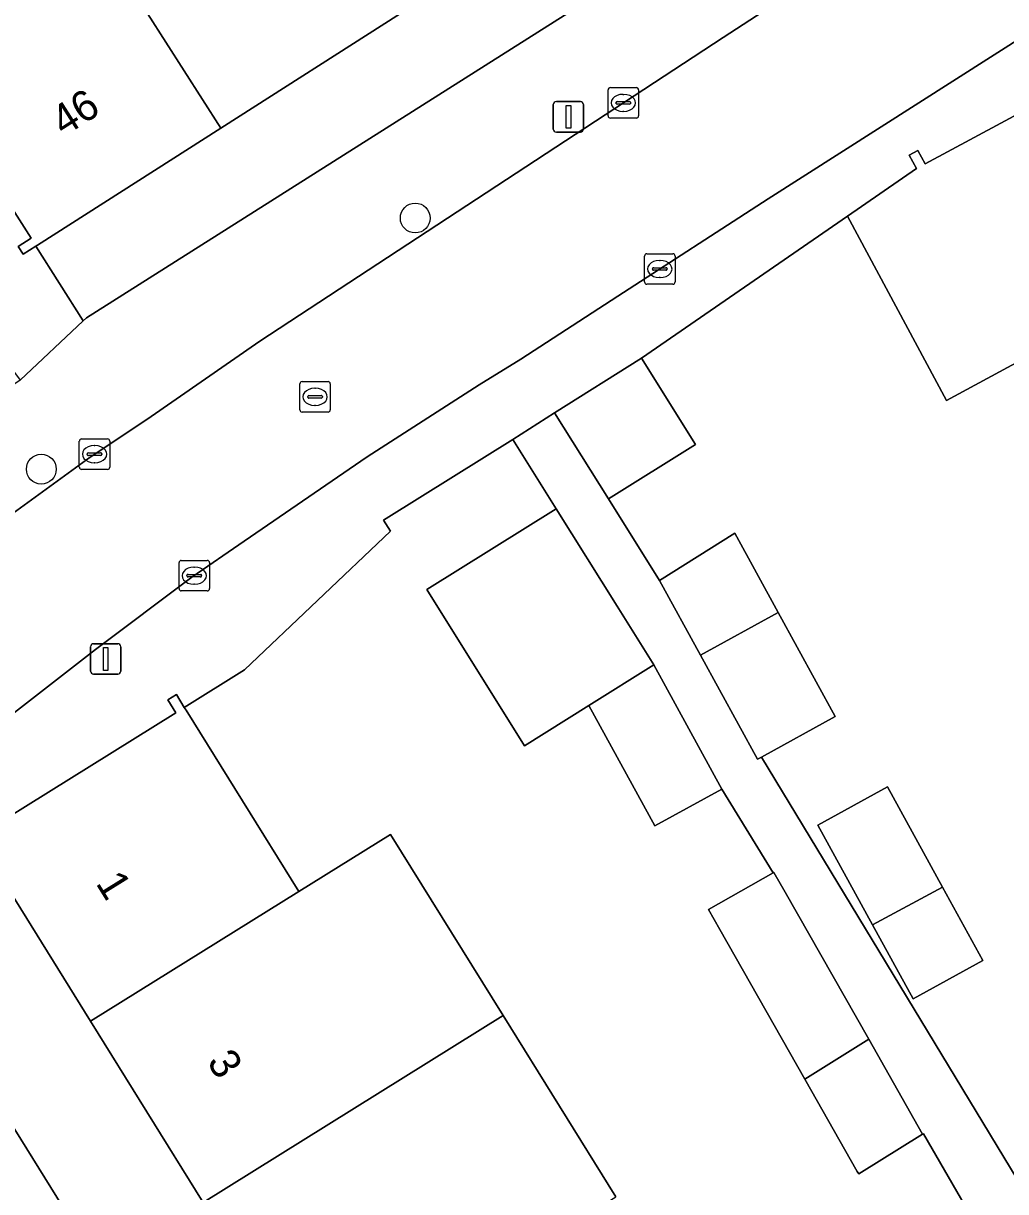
# Model space of a CAD drawing. Extents: x 162523 to 163266, y 381230 to 382050.
# Drawn here: x 162708.58 to 162740.82, y 381862.71 to 381901.03 of the extents above; entities that cross this region are included whole.
import ezdxf

# ---------------------------------------------------------------- set-up
doc = ezdxf.new("R2010")
doc.units = 0
for name, color, linetype in [('IMGEO_Boom', 7, 'Continuous'), ('IMGEO_Erf', 7, 'Continuous'), ('IMGEO_Kolk', 7, 'Continuous'), ('IMGEO_Lichtmast', 7, 'Continuous'), ('IMGEO_Muur', 7, 'Continuous'), ('IMGEO_Pand', 7, 'Continuous'), ('IMGEO_Pand_nummerreeks', 7, 'Continuous'), ('IMGEO_Rijbaan_lokaal_open', 7, 'Continuous'), ('IMGEO_Rioolput', 7, 'Continuous'), ('IMGEO_Voetpad_gesloten', 7, 'Continuous'), ('IMGEO_Voetpad_open', 7, 'Continuous')]:
    doc.layers.add(name, color=color, linetype=linetype)

msp = doc.modelspace()

# ---------------------------------------------------------------- linework, layer by layer
at = {"layer": 'IMGEO_Boom'}
for centre in [(162721.443, 381894.646), (162709.174, 381886.41)]:
    msp.add_circle(centre, 0.489, dxfattribs=at)
at = {"layer": 'IMGEO_Erf'}
for points in [[(162762.533, 381924.202), (162770.37, 381928.325), (162768.294, 381931.56), (162762.269, 381927.716), (162756.368, 381923.951), (162750.467, 381920.185), (162744.565, 381916.42), (162738.665, 381912.655), (162732.763, 381908.889), (162726.862, 381905.124), (162720.96, 381901.359), (162715.059, 381897.593), (162709.052, 381893.761), (162708.999, 381893.727), (162710.551, 381891.275), (162710.655, 381891.373)], [(162738.745, 381872.704), (162740.068, 381870.292), (162737.778, 381869.037), (162736.446, 381871.468), (162734.654, 381874.735), (162736.943, 381875.99)]]:
    msp.add_lwpolyline(points, close=True, dxfattribs=at)
for points in [[(162757.857, 381859.135), (162754.542, 381865.3), (162751.226, 381871.465), (162749.501, 381874.674), (162745.998, 381872.79), (162744.408, 381875.746), (162745.415, 381876.288), (162742.291, 381882.096), (162744.788, 381883.439), (162744.596, 381883.796), (162741.28, 381889.961), (162738.872, 381888.666), (162735.626, 381894.706), (162728.869, 381890.045), (162730.638, 381887.218), (162727.784, 381885.433), (162729.455, 381882.762), (162731.926, 381884.308), (162733.354, 381881.705), (162735.225, 381878.293), (162732.802, 381876.964), (162741.663, 381862.35), (162743.847, 381863.545), (162745.536, 381860.46)], [(162752.78, 381839.267), (162738.115, 381864.612), (162738.091, 381864.598), (162735.994, 381863.292), (162735.947, 381863.374), (162734.225, 381866.406), (162731.437, 381871.315), (162731.067, 381871.965), (162733.19, 381873.172), (162731.503, 381875.915), (162729.304, 381874.708), (162727.137, 381878.659), (162725.028, 381877.339), (162721.825, 381882.459), (162726.064, 381885.112), (162724.642, 381887.384), (162721.68, 381885.531), (162720.403, 381884.732), (162720.626, 381884.376), (162715.845, 381879.824), (162713.866, 381878.593), (162713.925, 381878.499), (162717.621, 381872.559), (162720.626, 381874.429), (162724.325, 381868.486), (162728.024, 381862.543)], [(162714.489, 381862.36), (162710.79, 381868.304), (162707.079, 381874.266), (162703.711, 381872.133), (162752.202, 381794.074)]]:
    msp.add_lwpolyline(points, dxfattribs=at)
at = {"layer": 'IMGEO_Kolk'}
for p, q in [((162727.771, 381897.996), (162727.771, 381898.848)), ((162727.846, 381898.922), (162728.698, 381898.922)), ((162728.259, 381898.702), (162728.284, 381898.702)), ((162728.772, 381898.848), (162728.772, 381897.996)), ((162728.03, 381898.416), (162728.03, 381898.428)), ((162728.468, 381898.379), (162728.07, 381898.379)), ((162728.073, 381898.465), (162728.471, 381898.465)), ((162728.514, 381898.428), (162728.514, 381898.416)), ((162728.698, 381897.922), (162727.846, 381897.922)), ((162728.282, 381898.142), (162728.257, 381898.142)), ((162728.966, 381892.548), (162728.966, 381893.4)), ((162729.041, 381893.474), (162729.893, 381893.474)), ((162729.967, 381893.4), (162729.967, 381892.548)), ((162729.225, 381892.968), (162729.225, 381892.98)), ((162729.663, 381892.931), (162729.265, 381892.931)), ((162729.268, 381893.017), (162729.666, 381893.017)), ((162729.454, 381893.254), (162729.479, 381893.254)), ((162729.709, 381892.98), (162729.709, 381892.968)), ((162729.477, 381892.694), (162729.452, 381892.694)), ((162729.893, 381892.474), (162729.041, 381892.474)), ((162710.421, 381886.475), (162710.421, 381887.327)), ((162710.496, 381887.401), (162711.348, 381887.401)), ((162710.909, 381887.181), (162710.934, 381887.181)), ((162711.422, 381887.327), (162711.422, 381886.475)), ((162710.68, 381886.895), (162710.68, 381886.907)), ((162711.118, 381886.858), (162710.72, 381886.858)), ((162710.723, 381886.944), (162711.121, 381886.944)), ((162711.164, 381886.907), (162711.164, 381886.895)), ((162711.348, 381886.401), (162710.496, 381886.401)), ((162710.932, 381886.621), (162710.907, 381886.621)), ((162713.692, 381882.49), (162713.692, 381883.342)), ((162713.767, 381883.416), (162714.619, 381883.416)), ((162714.693, 381883.342), (162714.693, 381882.49)), ((162713.994, 381882.959), (162714.392, 381882.959)), ((162714.18, 381883.196), (162714.205, 381883.196)), ((162713.951, 381882.91), (162713.951, 381882.922)), ((162714.389, 381882.873), (162713.991, 381882.873)), ((162714.203, 381882.636), (162714.178, 381882.636)), ((162714.435, 381882.922), (162714.435, 381882.91)), ((162714.619, 381882.416), (162713.767, 381882.416))]:
    msp.add_line(p, q, dxfattribs=at)
for points in [[(162727.771, 381897.996), (162727.771, 381898.848)], [(162727.846, 381898.922), (162728.698, 381898.922)], [(162728.772, 381898.848), (162728.772, 381897.996)], [(162728.698, 381897.922), (162727.846, 381897.922)], [(162728.966, 381892.548), (162728.966, 381893.4)], [(162729.041, 381893.474), (162729.893, 381893.474)], [(162729.967, 381893.4), (162729.967, 381892.548)], [(162729.893, 381892.474), (162729.041, 381892.474)], [(162710.421, 381886.475), (162710.421, 381887.327)], [(162710.496, 381887.401), (162711.348, 381887.401)], [(162711.422, 381887.327), (162711.422, 381886.475)], [(162711.348, 381886.401), (162710.496, 381886.401)], [(162713.692, 381882.49), (162713.692, 381883.342)], [(162713.767, 381883.416), (162714.619, 381883.416)], [(162714.693, 381883.342), (162714.693, 381882.49)], [(162714.619, 381882.416), (162713.767, 381882.416)]]:
    msp.add_lwpolyline(points, dxfattribs=at)
for centre, radius, start, end in [((162727.848, 381898.846), 0.0765, 91.552, 178.448), ((162727.848, 381898.846), 0.0765, 91.552, 178.448), ((162728.696, 381898.846), 0.0765, 1.552, 88.448), ((162728.696, 381898.846), 0.0765, 1.552, 88.448), ((162728.07, 381898.425), 0.0403, 85.8775, 175.7526), ((162728.067, 381898.415), 0.0366, 178.938, 274.7102), ((162728.471, 381898.422), 0.043, 264.8664, 352.4533), ((162728.475, 381898.427), 0.0386, 1.7309, 96.639), ((162727.848, 381897.998), 0.0765, 181.552, 268.448), ((162727.848, 381897.998), 0.0765, 181.552, 268.448), ((162728.696, 381897.998), 0.0765, 271.552, 358.448), ((162728.696, 381897.998), 0.0765, 271.552, 358.448), ((162729.043, 381893.398), 0.0765, 91.552, 178.448), ((162729.043, 381893.398), 0.0765, 91.552, 178.448), ((162729.891, 381893.398), 0.0765, 1.552, 88.448), ((162729.891, 381893.398), 0.0765, 1.552, 88.448), ((162729.265, 381892.977), 0.0403, 85.8775, 175.7526), ((162729.262, 381892.967), 0.0366, 178.938, 274.7102), ((162729.666, 381892.974), 0.043, 264.8664, 352.4533), ((162729.67, 381892.979), 0.0386, 1.7309, 96.639), ((162729.043, 381892.55), 0.0765, 181.552, 268.448), ((162729.043, 381892.55), 0.0765, 181.552, 268.448), ((162729.891, 381892.55), 0.0765, 271.552, 358.448), ((162729.891, 381892.55), 0.0765, 271.552, 358.448), ((162710.498, 381887.325), 0.0765, 91.552, 178.448), ((162710.498, 381887.325), 0.0765, 91.552, 178.448), ((162711.346, 381887.325), 0.0765, 1.552, 88.448), ((162711.346, 381887.325), 0.0765, 1.552, 88.448), ((162710.72, 381886.904), 0.0403, 85.8775, 175.7526), ((162710.717, 381886.894), 0.0366, 178.938, 274.7102), ((162711.121, 381886.901), 0.043, 264.8664, 352.4533), ((162711.125, 381886.906), 0.0386, 1.7309, 96.639), ((162710.498, 381886.477), 0.0765, 181.552, 268.448), ((162710.498, 381886.477), 0.0765, 181.552, 268.448), ((162711.346, 381886.477), 0.0765, 271.552, 358.448), ((162711.346, 381886.477), 0.0765, 271.552, 358.448), ((162713.769, 381883.34), 0.0765, 91.552, 178.448), ((162713.769, 381883.34), 0.0765, 91.552, 178.448), ((162714.617, 381883.34), 0.0765, 1.552, 88.448), ((162714.617, 381883.34), 0.0765, 1.552, 88.448), ((162713.991, 381882.919), 0.0403, 85.8775, 175.7526), ((162714.396, 381882.921), 0.0386, 1.7309, 96.639), ((162713.988, 381882.909), 0.0366, 178.938, 274.7102), ((162714.392, 381882.916), 0.043, 264.8664, 352.4533), ((162713.769, 381882.492), 0.0765, 181.552, 268.448), ((162713.769, 381882.492), 0.0765, 181.552, 268.448), ((162714.617, 381882.492), 0.0765, 271.552, 358.448), ((162714.617, 381882.492), 0.0765, 271.552, 358.448)]:
    msp.add_arc(centre, radius, start, end, dxfattribs=at)
for centre, major_axis, ratio, start_param, end_param in [((162728.258, 381898.422), (-0.387, 0.002), 0.722429, 4.712389, 7.853982), ((162728.283, 381898.422), (-0.39, 0.002), 0.717154, 1.570796, 4.712389), ((162729.453, 381892.974), (-0.387, 0.002), 0.722429, 4.712389, 7.853982), ((162729.478, 381892.974), (-0.39, 0.002), 0.717154, 1.570796, 4.712389), ((162710.908, 381886.901), (-0.387, 0.002), 0.722429, 4.712389, 7.853982), ((162710.933, 381886.901), (-0.39, 0.002), 0.717154, 1.570796, 4.712389), ((162714.179, 381882.916), (-0.387, 0.002), 0.722429, 4.712389, 7.853982), ((162714.204, 381882.916), (-0.39, 0.002), 0.717154, 1.570796, 4.712389)]:
    msp.add_ellipse(centre, major_axis=major_axis, ratio=ratio, start_param=start_param, end_param=end_param, dxfattribs=at)
at = {"layer": 'IMGEO_Lichtmast'}
for p, q in [((162725.974, 381897.564), (162725.974, 381898.364)), ((162725.974, 381898.364), (162725.974, 381897.564)), ((162726.074, 381898.464), (162726.864, 381898.464)), ((162726.864, 381898.464), (162726.074, 381898.464)), ((162726.964, 381898.364), (162726.964, 381897.564)), ((162726.964, 381897.564), (162726.964, 381898.364)), ((162726.864, 381897.464), (162726.074, 381897.464)), ((162726.074, 381897.464), (162726.864, 381897.464)), ((162710.891, 381880.684), (162711.681, 381880.684)), ((162711.681, 381880.684), (162710.891, 381880.684)), ((162710.791, 381879.784), (162710.791, 381880.584)), ((162710.791, 381880.584), (162710.791, 381879.784)), ((162711.781, 381880.584), (162711.781, 381879.784)), ((162711.781, 381879.784), (162711.781, 381880.584)), ((162711.681, 381879.684), (162710.891, 381879.684)), ((162710.891, 381879.684), (162711.681, 381879.684))]:
    msp.add_line(p, q, dxfattribs=at)
for points in [[(162726.394, 381898.339), (162726.544, 381898.339), (162726.544, 381897.589), (162726.394, 381897.589), (162726.394, 381898.339)], [(162711.211, 381880.559), (162711.361, 381880.559), (162711.361, 381879.809), (162711.211, 381879.809), (162711.211, 381880.559)]]:
    msp.add_lwpolyline(points, dxfattribs=at)
for centre, start, end in [((162726.074, 381898.364), 90, 180), ((162726.074, 381898.364), 90, 180), ((162726.864, 381898.364), 0, 90), ((162726.864, 381898.364), 360, 90), ((162726.074, 381897.564), 180, 270), ((162726.074, 381897.564), 180, 270), ((162726.864, 381897.564), 270, 0), ((162726.864, 381897.564), 270, 0), ((162710.891, 381880.584), 90, 180), ((162710.891, 381880.584), 90, 180), ((162711.681, 381880.584), 0, 90), ((162711.681, 381880.584), 360, 90), ((162710.891, 381879.784), 180, 270), ((162710.891, 381879.784), 180, 270), ((162711.681, 381879.784), 270, 0), ((162711.681, 381879.784), 270, 0)]:
    msp.add_arc(centre, 0.1, start, end, dxfattribs=at)
at = {"layer": 'IMGEO_Muur'}
for points in [[(162728.869, 381890.045), (162735.626, 381894.706)], [(162720.626, 381884.376), (162715.845, 381879.824), (162713.866, 381878.593)]]:
    msp.add_lwpolyline(points, dxfattribs=at)
at = {"layer": 'IMGEO_Pand'}
for points in [[(162709.051, 381907.003), (162715.059, 381897.593), (162720.96, 381901.359), (162714.952, 381910.768)], [(162709.051, 381907.003), (162705.824, 381904.944), (162701.032, 381901.887), (162705.545, 381894.814), (162707.506, 381896.065), (162708.837, 381893.981), (162708.417, 381893.713), (162708.579, 381893.459), (162708.999, 381893.727), (162709.052, 381893.761), (162715.059, 381897.593)], [(162748.419, 381893.798), (162745.066, 381900.034), (162744.791, 381900.545), (162744.509, 381900.392), (162744.745, 381899.951), (162738.173, 381896.419), (162737.936, 381896.86), (162737.654, 381896.708), (162737.89, 381896.267), (162735.626, 381894.706), (162738.872, 381888.666), (162741.28, 381889.961)], [(162730.638, 381887.218), (162728.869, 381890.045), (162726.015, 381888.26), (162727.784, 381885.433)], [(162726.064, 381885.112), (162721.825, 381882.459), (162725.028, 381877.339), (162727.137, 381878.659), (162729.267, 381879.992), (162728.067, 381881.91)], [(162731.926, 381884.308), (162729.455, 381882.762), (162730.802, 381880.306), (162733.354, 381881.705)], [(162733.354, 381881.705), (162730.802, 381880.306), (162732.674, 381876.894), (162732.802, 381876.964), (162735.225, 381878.293)], [(162729.267, 381879.992), (162727.137, 381878.659), (162729.304, 381874.708), (162731.503, 381875.915)], [(162710.79, 381868.304), (162717.621, 381872.559), (162713.925, 381878.499), (162713.866, 381878.593), (162713.604, 381879.014), (162713.326, 381878.84), (162713.587, 381878.419), (162707.313, 381874.515), (162707.05, 381874.935), (162706.771, 381874.762), (162707.079, 381874.266)], [(162736.446, 381871.468), (162738.745, 381872.704), (162736.943, 381875.99), (162734.654, 381874.735)], [(162724.325, 381868.486), (162720.626, 381874.429), (162717.621, 381872.559), (162710.79, 381868.304), (162714.489, 381862.36)], [(162733.583, 381872.534), (162733.213, 381873.185), (162733.19, 381873.172), (162731.067, 381871.965), (162731.437, 381871.315), (162734.225, 381866.406), (162736.322, 381867.712)], [(162736.446, 381871.468), (162737.778, 381869.037), (162740.068, 381870.292), (162738.745, 381872.704)], [(162718.187, 381856.418), (162725.018, 381860.672), (162728.024, 381862.543), (162724.325, 381868.486), (162714.489, 381862.36)], [(162738.091, 381864.598), (162736.322, 381867.712), (162734.225, 381866.406), (162735.947, 381863.374), (162735.994, 381863.292)]]:
    msp.add_lwpolyline(points, close=True, dxfattribs=at)
at = {"layer": 'IMGEO_Rijbaan_lokaal_open'}
msp.add_lwpolyline([(162728.092, 381892.085), (162733.021, 381895.276), (162746.493, 381903.872), (162747.117, 381904.27), (162753.065, 381908.037), (162757.37, 381910.766), (162754.588, 381915.413), (162753.541, 381914.762), (162746.002, 381909.969), (162731.552, 381900.569), (162716.347, 381890.607), (162712.639, 381888.043), (162710.772, 381886.8), (162705.831, 381883.214), (162702.789, 381880.999), (162700.595, 381879.197), (162704.065, 381874.976), (162707.792, 381878.046), (162710.957, 381880.489), (162714.111, 381882.861), (162715.828, 381884.045), (162719.862, 381886.809), (162723.541, 381889.18), (162724.903, 381890.021)], close=True, dxfattribs=at)
at = {"layer": 'IMGEO_Rioolput'}
for p, q in [((162717.655, 381888.355), (162717.655, 381889.207)), ((162717.73, 381889.281), (162718.582, 381889.281)), ((162718.656, 381889.207), (162718.656, 381888.355)), ((162717.914, 381888.775), (162717.914, 381888.787)), ((162718.352, 381888.738), (162717.954, 381888.738)), ((162717.957, 381888.824), (162718.355, 381888.824)), ((162718.143, 381889.061), (162718.168, 381889.061)), ((162718.398, 381888.787), (162718.398, 381888.775)), ((162718.166, 381888.501), (162718.141, 381888.501)), ((162718.582, 381888.281), (162717.73, 381888.281))]:
    msp.add_line(p, q, dxfattribs=at)
for points in [[(162717.655, 381888.355), (162717.655, 381889.207)], [(162717.73, 381889.281), (162718.582, 381889.281)], [(162718.656, 381889.207), (162718.656, 381888.355)], [(162718.582, 381888.281), (162717.73, 381888.281)]]:
    msp.add_lwpolyline(points, dxfattribs=at)
for centre, radius, start, end in [((162717.732, 381889.205), 0.0765, 91.552, 178.448), ((162717.732, 381889.205), 0.0765, 91.552, 178.448), ((162718.58, 381889.205), 0.0765, 1.552, 88.448), ((162718.58, 381889.205), 0.0765, 1.552, 88.448), ((162717.954, 381888.784), 0.0403, 85.8775, 175.7526), ((162717.951, 381888.774), 0.0366, 178.938, 274.7102), ((162718.355, 381888.781), 0.043, 264.8664, 352.4533), ((162718.359, 381888.786), 0.0386, 1.7309, 96.639), ((162717.732, 381888.357), 0.0765, 181.552, 268.448), ((162717.732, 381888.357), 0.0765, 181.552, 268.448), ((162718.58, 381888.357), 0.0765, 271.552, 358.448), ((162718.58, 381888.357), 0.0765, 271.552, 358.448)]:
    msp.add_arc(centre, radius, start, end, dxfattribs=at)
for centre, major_axis, ratio, start_param, end_param in [((162718.142, 381888.781), (-0.387, 0.002), 0.722429, 4.712389, 7.853982), ((162718.167, 381888.781), (-0.39, 0.002), 0.717154, 1.570796, 4.712389)]:
    msp.add_ellipse(centre, major_axis=major_axis, ratio=ratio, start_param=start_param, end_param=end_param, dxfattribs=at)
at = {"layer": 'IMGEO_Voetpad_gesloten'}
for points in [[(162810.161, 381941.78), (162808.646, 381941.198), (162801.594, 381938.69), (162786.343, 381934.002), (162784.884, 381933.543), (162780.446, 381932.147), (162777.331, 381931.33), (162775.579, 381930.87), (162770.37, 381928.325), (162762.533, 381924.202), (162710.655, 381891.373), (162710.551, 381891.275), (162708.484, 381889.327), (162705.634, 381887.408), (162659.283, 381849.513)], [(162672.848, 381856.46), (162681.316, 381863.363), (162688.855, 381869.619), (162694.996, 381874.59), (162695.513, 381875.009), (162700.595, 381879.197), (162702.789, 381880.999), (162705.831, 381883.214), (162710.772, 381886.8), (162712.639, 381888.043), (162716.347, 381890.607), (162731.552, 381900.569), (162746.002, 381909.969), (162753.541, 381914.762), (162754.588, 381915.413), (162760.8, 381919.183)]]:
    msp.add_lwpolyline(points, dxfattribs=at)
at = {"layer": 'IMGEO_Voetpad_open'}
for points in [[(162765.264, 381915.753), (162763.541, 381914.667), (162760.275, 381912.607), (162757.37, 381910.766), (162753.065, 381908.037), (162747.117, 381904.27), (162746.493, 381903.872), (162733.021, 381895.276), (162728.092, 381892.085), (162724.903, 381890.021), (162723.541, 381889.18), (162719.862, 381886.809), (162715.828, 381884.045), (162714.111, 381882.861), (162710.957, 381880.489), (162707.792, 381878.046), (162704.065, 381874.976), (162702.51, 381873.695), (162698.457, 381870.411), (162695.216, 381867.785)], [(162695.028, 381905.666), (162699.084, 381900.707), (162699.158, 381900.768), (162701.263, 381898.194), (162701.356, 381898.27), (162703.292, 381895.906), (162706.254, 381892.289), (162706.551, 381892.533), (162706.757, 381892.281), (162706.449, 381892.03), (162708.484, 381889.327), (162710.551, 381891.275), (162708.999, 381893.727), (162708.579, 381893.459), (162708.417, 381893.713), (162708.837, 381893.981), (162707.506, 381896.065), (162705.545, 381894.814), (162701.032, 381901.887)], [(162707.313, 381874.515), (162713.587, 381878.419), (162713.326, 381878.84), (162713.604, 381879.014), (162713.866, 381878.593), (162715.845, 381879.824), (162720.626, 381884.376), (162720.403, 381884.732), (162721.68, 381885.531), (162724.642, 381887.384), (162726.015, 381888.26), (162728.869, 381890.045), (162735.626, 381894.706), (162737.89, 381896.267), (162737.654, 381896.708), (162737.936, 381896.86), (162738.173, 381896.419), (162744.745, 381899.951)], [(162741.663, 381862.35), (162732.802, 381876.964), (162732.674, 381876.894), (162730.802, 381880.306), (162729.455, 381882.762), (162727.784, 381885.433), (162726.015, 381888.26), (162724.642, 381887.384), (162726.064, 381885.112), (162728.067, 381881.91), (162729.267, 381879.992), (162731.503, 381875.915), (162733.19, 381873.172), (162733.213, 381873.185), (162733.583, 381872.534), (162736.322, 381867.712), (162738.091, 381864.598), (162738.115, 381864.612), (162752.78, 381839.267)], [(162747.925, 381792.231), (162752.202, 381794.074), (162703.711, 381872.133)]]:
    msp.add_lwpolyline(points, dxfattribs=at)

# ---------------------------------------------------------------- texts
at = {"layer": 'IMGEO_Pand_nummerreeks'}
for s, rotation, p in [('46', 32.5383, (162709.914, 381897.3)), ('1', 301.8952, (162710.941, 381872.83)), ('3', 301.8952, (162714.589, 381866.97))]:
    msp.add_text(s, height=1, rotation=rotation, dxfattribs=at).set_placement(p)

doc.saveas('drawing.dxf')
